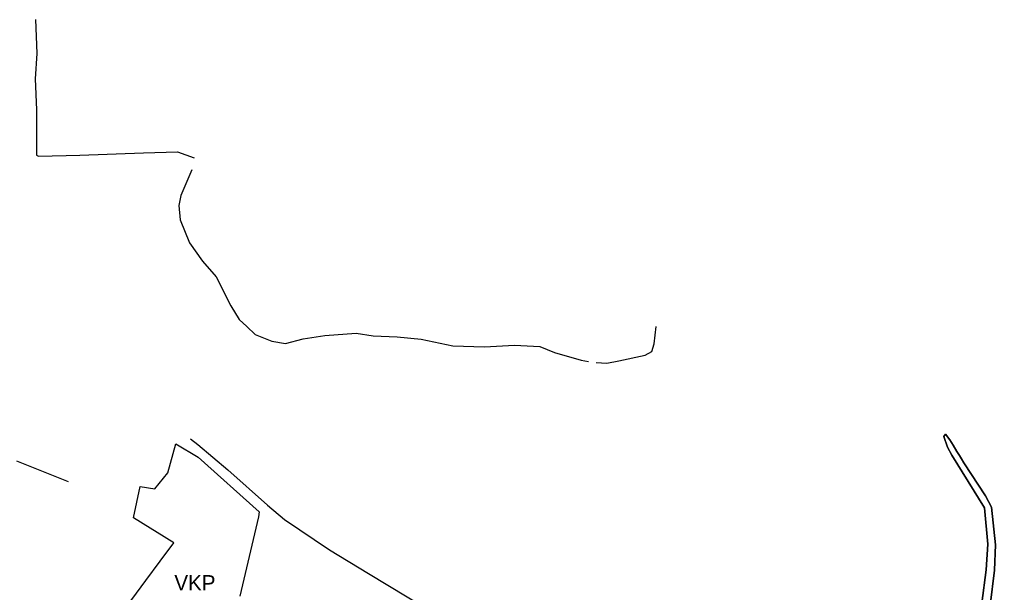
# Model space of a CAD drawing. Extents: x -555426 to -553015, y -1186745 to -1182595.
# Drawn here: x -554287 to -553015, y -1185506 to -1184759 of the extents above; entities that cross this region are included whole.
import ezdxf

# ---------------------------------------------------------------- set-up
doc = ezdxf.new("R2010")
doc.units = 0
for name, color, linetype in [('Level 10', 7, 'Continuous'), ('Level 12', 7, 'Continuous'), ('Level 51', 7, 'Continuous'), ('USES_LBK_stav', 7, 'Continuous')]:
    doc.layers.add(name, color=color, linetype=linetype)

msp = doc.modelspace()

# ---------------------------------------------------------------- linework, layer by layer
at = {"layer": 'Level 10'}
msp.add_lwpolyline([(-554153.6, -1185532.9), (-554122.2, -1185490.3), (-554103.4, -1185465), (-554085.8, -1185441.1), (-554138.3, -1185408.4), (-554129.4, -1185367.4), (-554110.3, -1185370.8), (-554093.4, -1185349.6), (-554082.9, -1185312), (-554053.8, -1185329.2), (-553974.4, -1185400.7), (-553975.4, -1185407.1), (-553999.7, -1185510.6)], dxfattribs=at)
at = {"layer": 'Level 12'}
for points in [[(-553034.9, -1185564.7), (-553030.1, -1185550.4), (-553022.2, -1185522.5), (-553016.8, -1185476.6), (-553015.4, -1185443.7), (-553020.8, -1185394.6), (-553028.5, -1185379.7), (-553056.7, -1185336.8), (-553059.8, -1185331.6), (-553062.3, -1185327.4), (-553065.6, -1185322), (-553070.5, -1185313.9), (-553074.8, -1185306.8), (-553080.4, -1185299.2), (-553082.9, -1185302.3)], [(-553082.9, -1185302.3), (-553078.1, -1185316.3), (-553072.2, -1185326.7), (-553029.8, -1185395.3), (-553025.3, -1185442.9), (-553027.5, -1185476.2), (-553033.3, -1185519.7)]]:
    msp.add_lwpolyline(points, dxfattribs=at)
at = {"layer": 'Level 51'}
for points in [[(-554265.6, -1184759.1), (-554264.2, -1184803.2), (-554266.1, -1184836.3), (-554264.7, -1184876.8), (-554264.3, -1184917.8), (-554264.6, -1184935.7), (-554262.1, -1184937.3), (-554208, -1184935.8), (-554125.1, -1184933), (-554080.9, -1184931.6), (-554059.3, -1184939.4)], [(-554062.3, -1184955.1), (-554076.4, -1184988.4), (-554079.2, -1185001.5), (-554077.2, -1185020.3), (-554065.4, -1185050), (-554048.3, -1185074), (-554030.3, -1185094.6), (-554011.5, -1185132.1), (-554000.4, -1185150.2), (-553990.7, -1185159.3), (-553979.8, -1185169.6), (-553958, -1185178.1), (-553940.3, -1185181.1), (-553917.2, -1185175), (-553889.1, -1185170.9), (-553848.2, -1185167.6), (-553826.1, -1185171.2), (-553794.6, -1185172.7), (-553763.4, -1185175.7), (-553722.3, -1185184.3), (-553680.9, -1185185.4), (-553642, -1185183.6), (-553609.1, -1185185.1), (-553589.9, -1185193.2), (-553555.3, -1185203.1), (-553545.7, -1185204.9)], [(-553535.4, -1185205.8), (-553521.5, -1185206.9), (-553505.9, -1185203.9), (-553471.9, -1185196.6), (-553463, -1185191.7), (-553460.1, -1185181.6), (-553457.4, -1185159.3)], [(-554064, -1185305.3), (-554054.3, -1185313), (-554015.3, -1185345.9), (-553963.7, -1185392), (-553941.6, -1185410.7), (-553882.9, -1185450.1), (-553831.9, -1185481.1), (-553729.3, -1185543.1), (-553648, -1185592.3), (-553613.8, -1185613.3)], [(-554290.4, -1185334.3), (-554223.3, -1185361.3)]]:
    msp.add_lwpolyline(points, dxfattribs=at)
at = {"layer": 'USES_LBK_stav'}
for points in [[(-553082.9, -1185302.3), (-553080.4, -1185299.2), (-553074.8, -1185306.8), (-553070.5, -1185313.9), (-553065.6, -1185322), (-553062.3, -1185327.4), (-553059.8, -1185331.6), (-553056.7, -1185336.8), (-553028.5, -1185379.7), (-553020.8, -1185394.6), (-553015.4, -1185443.7), (-553016.8, -1185476.6), (-553022.2, -1185522.5), (-553030.1, -1185550.4), (-553034.9, -1185564.7)], [(-553033.3, -1185519.7), (-553027.5, -1185476.2), (-553025.3, -1185442.9), (-553029.8, -1185395.3), (-553072.2, -1185326.7), (-553078.1, -1185316.3), (-553082.9, -1185302.3)]]:
    msp.add_lwpolyline(points, dxfattribs=at)

# ---------------------------------------------------------------- texts
at = {"layer": 'Level 10'}
msp.add_text('VKP', height=20, dxfattribs=at).set_placement((-554084.9, -1185503.1))

doc.saveas('drawing.dxf')
